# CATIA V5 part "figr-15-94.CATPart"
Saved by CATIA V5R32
Part number: Part1
Bounding box of the stored display mesh (mm): x -40 to 40, y -60 to 60, z -4 to 2
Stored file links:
  D:\PROJECTS\Project 2022\CATIA V5 6R 2022\Resources\Part Files\c15_catia_v5_6r2022_prt\figr-15-94.CATPart
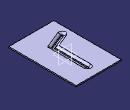
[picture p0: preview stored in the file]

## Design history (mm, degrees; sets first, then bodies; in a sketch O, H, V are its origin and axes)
SheetMetalParameters1: Thickness 2, BendRadius 4, KFactor 0.400515 {= log(min(100,max(20*SheetMetalParameters1.BendRadius,SheetMetalParameters1.Thickness)/SheetMetalParameters1.Thickness))/log(100)/2}, ReliefRadialLength 1, ReliefAxialLength 2, MinimumBendRadius 0
Body1 (main body)
  Sketch1 on xy-plane, origin (0, 0, 0), H (-1, 0, 0), V (0, -1, 0)
    line L1 (40, 60) -> (40, -60)
    line L2 (40, -60) -> (-40, -60)
    line L3 (-40, -60) -> (-40, 60)
    line L4 (-40, 60) -> (40, 60)
    length L4 = 80
    length L1 = 120
    vertical: L1 V, L3 V
    horizontal: L2 H, L4 H
    equidistance: L1 L3 O, L2 L4 O
  Wall1: Thickness 2, Profile Sketch1, OffsetValue 0
  Sketch2 on face of Wall1, origin (0, 0, 2), H (1, 0, 0), V (0, 1, 0)
    line L1 (0, 40.0798) -> (0, -21.0085)
    line L2 (0, -21.0085) -> (-27, -32)
    vertical: L1 V
  d_Stamp1: NewRoot_AttribNormalisation "No Standard", Stamp_FilletRadius 2, Stamp_IntersectFilletRadius 2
